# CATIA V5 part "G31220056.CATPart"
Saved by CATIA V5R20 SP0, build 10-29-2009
Part number: G31220056
Revision: 10
Definition: design
Nomenclature: G31220056
Source: made
Description: NOT SPECIFIED
Bounding box of the stored display mesh (mm): x -8 to 56, y -15.5 to 15.5, z -15.5 to 15.5
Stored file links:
  C:\Users\Raffaele\Desktop\3D X SITO CF\BOLEX\23-BUSH REF 312\G31220056.CATPart

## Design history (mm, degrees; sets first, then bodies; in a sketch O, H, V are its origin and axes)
Body1 "MANIFOLD_SOLID_BREP #14883" (main body)
  Solid1: solid without history
Body2 "MANIFOLD_SOLID_BREP #15030"
  Solid2: solid without history
Body3 "MANIFOLD_SOLID_BREP #15177"
  Solid3: solid without history
Body4 "MANIFOLD_SOLID_BREP #15324"
  Solid4: solid without history
Body5 "MANIFOLD_SOLID_BREP #15471"
  Solid5: solid without history
Body6 "MANIFOLD_SOLID_BREP #15616"
  Solid6: solid without history
Body7 "MANIFOLD_SOLID_BREP #15761"
  Solid7: solid without history
Body8 "MANIFOLD_SOLID_BREP #15910"
  Solid8: solid without history
Body9 "MANIFOLD_SOLID_BREP #16059"
  Solid9: solid without history
Body10 "MANIFOLD_SOLID_BREP #16204"
  Solid10: solid without history
Body11 "MANIFOLD_SOLID_BREP #16349"
  Solid11: solid without history
Body12 "MANIFOLD_SOLID_BREP #16494"
  Solid12: solid without history
Body13 "MANIFOLD_SOLID_BREP #16639"
  Solid13: solid without history
Body14 "MANIFOLD_SOLID_BREP #16788"
  Solid14: solid without history
Body15 "MANIFOLD_SOLID_BREP #16937"
  Solid15: solid without history
Body16 "MANIFOLD_SOLID_BREP #17082"
  Solid16: solid without history
Body17 "MANIFOLD_SOLID_BREP #17227"
  Solid17: solid without history
Body18 "MANIFOLD_SOLID_BREP #17372"
  Solid18: solid without history
Body19 "MANIFOLD_SOLID_BREP #17517"
  Solid19: solid without history
Body20 "MANIFOLD_SOLID_BREP #17662"
  Solid20: solid without history
Body21 "MANIFOLD_SOLID_BREP #17807"
  Solid21: solid without history
Body22 "MANIFOLD_SOLID_BREP #17954"
  Solid22: solid without history
Body23 "MANIFOLD_SOLID_BREP #18099"
  Solid23: solid without history
Body24 "MANIFOLD_SOLID_BREP #18244"
  Solid24: solid without history
Body25 "MANIFOLD_SOLID_BREP #18391"
  Solid25: solid without history
Body26 "MANIFOLD_SOLID_BREP #18536"
  Solid26: solid without history
Body27 "MANIFOLD_SOLID_BREP #18685"
  Solid27: solid without history
Body28 "MANIFOLD_SOLID_BREP #18830"
  Solid28: solid without history
Body29 "MANIFOLD_SOLID_BREP #18975"
  Solid29: solid without history
Body30 "MANIFOLD_SOLID_BREP #19124"
  Solid30: solid without history
Body31 "MANIFOLD_SOLID_BREP #19269"
  Solid31: solid without history
Body32 "MANIFOLD_SOLID_BREP #19416"
  Solid32: solid without history
Body33 "MANIFOLD_SOLID_BREP #19563"
  Solid33: solid without history
Body34 "MANIFOLD_SOLID_BREP #19708"
  Solid34: solid without history
Body35 "MANIFOLD_SOLID_BREP #19853"
  Solid35: solid without history
Body36 "MANIFOLD_SOLID_BREP #19998"
  Solid36: solid without history
Body37 "MANIFOLD_SOLID_BREP #20143"
  Solid37: solid without history
Body38 "MANIFOLD_SOLID_BREP #20290"
  Solid38: solid without history
Body39 "MANIFOLD_SOLID_BREP #20435"
  Solid39: solid without history
Body40 "MANIFOLD_SOLID_BREP #20580"
  Solid40: solid without history
Body41 "MANIFOLD_SOLID_BREP #20727"
  Solid41: solid without history
Body42 "MANIFOLD_SOLID_BREP #20872"
  Solid42: solid without history
Body43 "MANIFOLD_SOLID_BREP #21021"
  Solid43: solid without history
Body44 "MANIFOLD_SOLID_BREP #21166"
  Solid44: solid without history
Body45 "MANIFOLD_SOLID_BREP #21311"
  Solid45: solid without history
Body46 "MANIFOLD_SOLID_BREP #21460"
  Solid46: solid without history
Body47 "MANIFOLD_SOLID_BREP #21605"
  Solid47: solid without history
Body48 "MANIFOLD_SOLID_BREP #21750"
  Solid48: solid without history
Body49 "MANIFOLD_SOLID_BREP #21895"
  Solid49: solid without history
Body50 "MANIFOLD_SOLID_BREP #22040"
  Solid50: solid without history
Body51 "MANIFOLD_SOLID_BREP #22185"
  Solid51: solid without history
Body52 "MANIFOLD_SOLID_BREP #22332"
  Solid52: solid without history
Body53 "MANIFOLD_SOLID_BREP #22477"
  Solid53: solid without history
Body54 "MANIFOLD_SOLID_BREP #22622"
  Solid54: solid without history
Body55 "MANIFOLD_SOLID_BREP #22769"
  Solid55: solid without history
Body56 "MANIFOLD_SOLID_BREP #22916"
  Solid56: solid without history
Body57 "MANIFOLD_SOLID_BREP #23063"
  Solid57: solid without history
Body58 "MANIFOLD_SOLID_BREP #23208"
  Solid58: solid without history
Body59 "MANIFOLD_SOLID_BREP #23357"
  Solid59: solid without history
Body60 "MANIFOLD_SOLID_BREP #23502"
  Solid60: solid without history
Body61 "MANIFOLD_SOLID_BREP #23647"
  Solid61: solid without history
Body62 "MANIFOLD_SOLID_BREP #23796"
  Solid62: solid without history
Body63 "MANIFOLD_SOLID_BREP #23941"
  Solid63: solid without history
Body64 "MANIFOLD_SOLID_BREP #24088"
  Solid64: solid without history
Body65 "MANIFOLD_SOLID_BREP #24235"
  Solid65: solid without history
Body66 "MANIFOLD_SOLID_BREP #24380"
  Solid66: solid without history
Body67 "MANIFOLD_SOLID_BREP #24525"
  Solid67: solid without history
Body68 "MANIFOLD_SOLID_BREP #24670"
  Solid68: solid without history
Body69 "MANIFOLD_SOLID_BREP #24815"
  Solid69: solid without history
Body70 "MANIFOLD_SOLID_BREP #24962"
  Solid70: solid without history
Body71 "MANIFOLD_SOLID_BREP #25107"
  Solid71: solid without history
Body72 "MANIFOLD_SOLID_BREP #25252"
  Solid72: solid without history
Body73 "MANIFOLD_SOLID_BREP #25399"
  Solid73: solid without history
Body74 "MANIFOLD_SOLID_BREP #25544"
  Solid74: solid without history
Body75 "MANIFOLD_SOLID_BREP #25689"
  Solid75: solid without history
Body76 "MANIFOLD_SOLID_BREP #25838"
  Solid76: solid without history
Body77 "MANIFOLD_SOLID_BREP #25987"
  Solid77: solid without history
Body78 "MANIFOLD_SOLID_BREP #26132"
  Solid78: solid without history
Body79 "MANIFOLD_SOLID_BREP #26277"
  Solid79: solid without history
Body80 "MANIFOLD_SOLID_BREP #26422"
  Solid80: solid without history
Body81 "MANIFOLD_SOLID_BREP #26567"
  Solid81: solid without history
Body82 "MANIFOLD_SOLID_BREP #26716"
  Solid82: solid without history
Body83 "MANIFOLD_SOLID_BREP #26865"
  Solid83: solid without history
Body84 "MANIFOLD_SOLID_BREP #27010"
  Solid84: solid without history
Body85 "MANIFOLD_SOLID_BREP #27155"
  Solid85: solid without history
Body86 "MANIFOLD_SOLID_BREP #27302"
  Solid86: solid without history
Body87 "MANIFOLD_SOLID_BREP #27449"
  Solid87: solid without history
Body88 "MANIFOLD_SOLID_BREP #27596"
  Solid88: solid without history
Body89 "MANIFOLD_SOLID_BREP #27743"
  Solid89: solid without history
Body90 "MANIFOLD_SOLID_BREP #27888"
  Solid90: solid without history
Body91 "MANIFOLD_SOLID_BREP #28033"
  Solid91: solid without history
Body92 "MANIFOLD_SOLID_BREP #28178"
  Solid92: solid without history
Body93 "MANIFOLD_SOLID_BREP #28323"
  Solid93: solid without history
Body94 "MANIFOLD_SOLID_BREP #28468"
  Solid94: solid without history
Body95 "MANIFOLD_SOLID_BREP #28613"
  Solid95: solid without history
Body96 "MANIFOLD_SOLID_BREP #28758"
  Solid96: solid without history
Body97 "MANIFOLD_SOLID_BREP #28903"
  Solid97: solid without history
Body98 "MANIFOLD_SOLID_BREP #29050"
  Solid98: solid without history
Body99 "MANIFOLD_SOLID_BREP #29197"
  Solid99: solid without history
Body100 "MANIFOLD_SOLID_BREP #29342"
  Solid100: solid without history
Body101 "MANIFOLD_SOLID_BREP #29487"
  Solid101: solid without history
Body102 "MANIFOLD_SOLID_BREP #29632"
  Solid102: solid without history
Body103 "MANIFOLD_SOLID_BREP #29777"
  Solid103: solid without history
Body104 "MANIFOLD_SOLID_BREP #29924"
  Solid104: solid without history
Body105 "MANIFOLD_SOLID_BREP #30071"
  Solid105: solid without history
